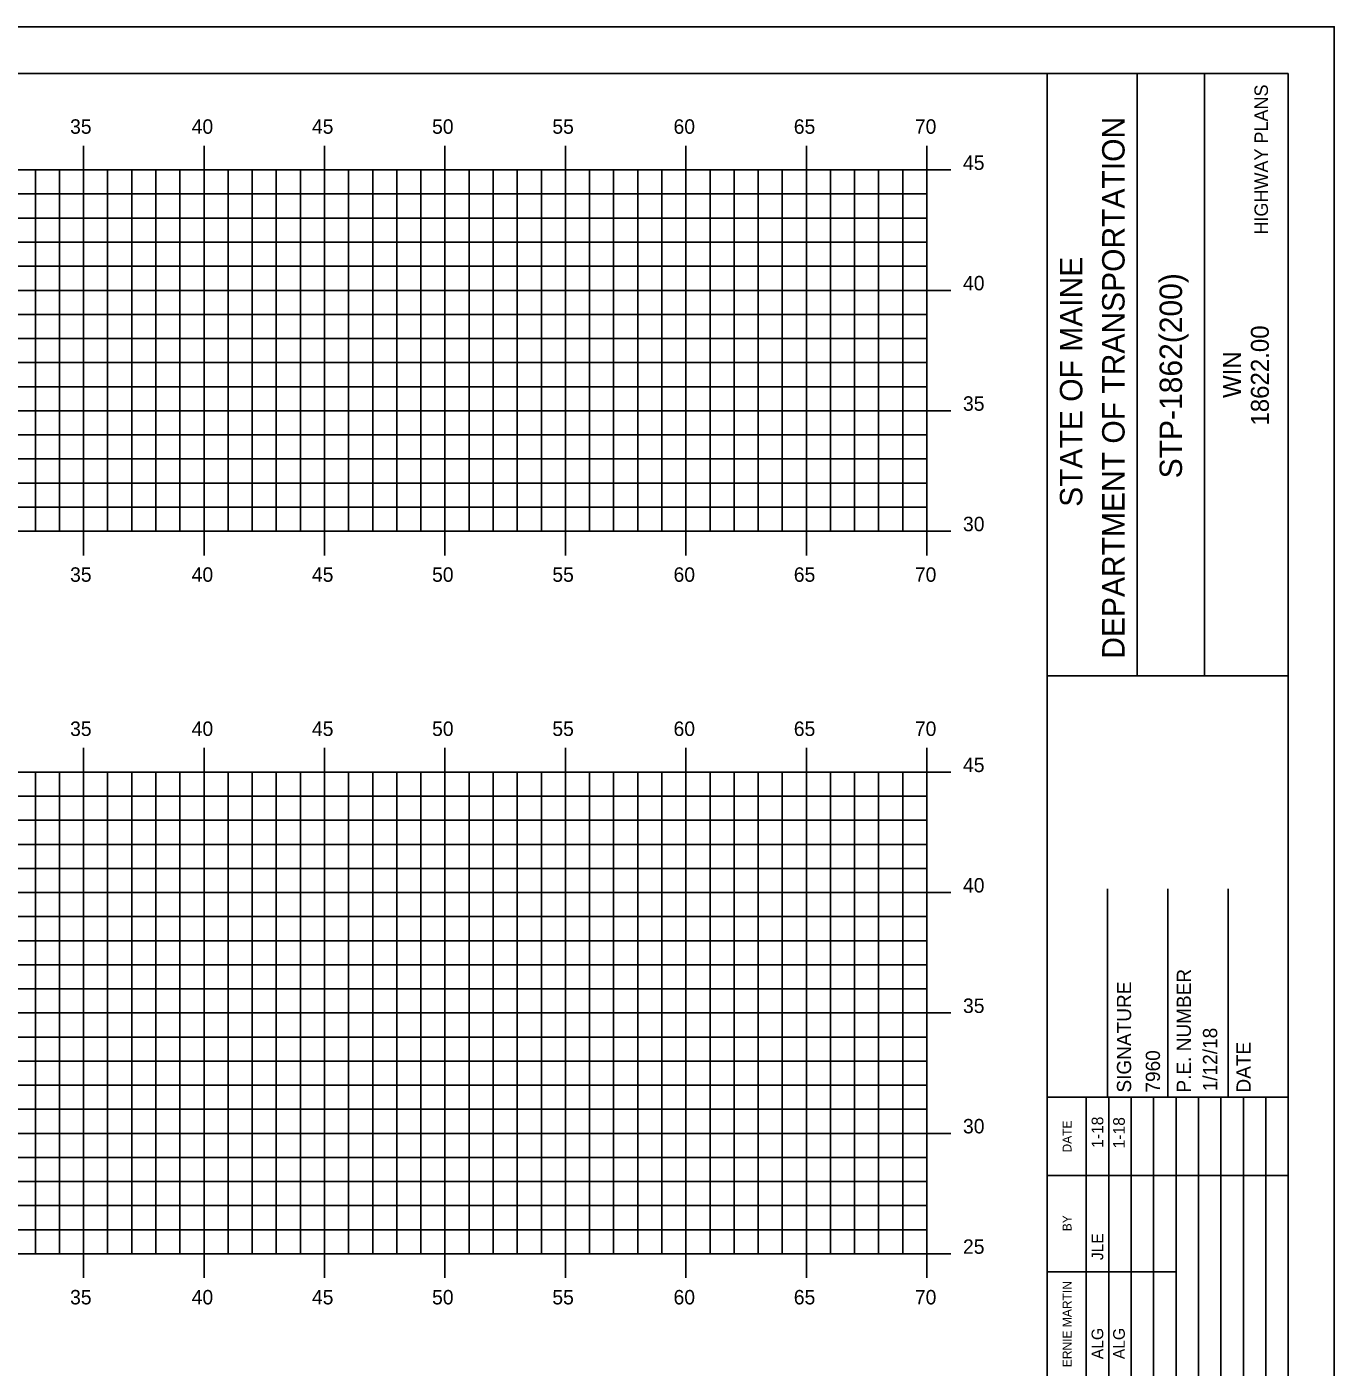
# Model space of a CAD drawing. Extents: x 1026799 to 1026969, y 394697 to 394807.
# Drawn here: x 1026915 to 1026969.3, y 394750.9 to 394806.5 of the extents above; entities that cross this region are included whole.
import ezdxf

# ---------------------------------------------------------------- set-up
doc = ezdxf.new("R2010")
doc.units = 0
for name, color, linetype in [('BORDER', 7, 'Continuous'), ('H_V ANNOTATION', 7, 'Continuous'), ('HIGHWAY_TITLE', 7, 'Continuous'), ('MAJOR', 7, 'Continuous'), ('MINOR', 7, 'Continuous'), ('PLOT BOUNDARY', 7, 'Continuous')]:
    doc.layers.add(name, color=color, linetype=linetype)

msp = doc.modelspace()

# ---------------------------------------------------------------- linework, layer by layer
at = {"layer": 'BORDER'}
for p, q in [((1026967.348, 394804.607), (1026807.348, 394804.607)), ((1026957.348, 394699.607), (1026957.348, 394804.61)), ((1026961.076, 394779.604), (1026961.076, 394804.604)), ((1026963.871, 394779.604), (1026963.871, 394804.604)), ((1026967.348, 394699.607), (1026967.348, 394804.607)), ((1026957.349, 394779.601), (1026967.348, 394779.601)), ((1026959.848, 394762.11), (1026959.848, 394770.757)), ((1026962.348, 394762.11), (1026962.348, 394770.757)), ((1026964.848, 394762.11), (1026964.848, 394770.757)), ((1026957.348, 394762.11), (1026967.348, 394762.11))]:
    msp.add_line(p, q, dxfattribs=at)
for points in [[(1026958.963, 394758.86), (1026958.963, 394762.11)], [(1026959.895, 394744.613), (1026959.895, 394762.11)], [(1026960.827, 394762.11), (1026960.827, 394744.613)], [(1026961.759, 394744.613), (1026961.759, 394762.11)], [(1026962.69, 394744.613), (1026962.69, 394762.11)], [(1026963.622, 394744.613), (1026963.622, 394762.11)], [(1026964.554, 394744.613), (1026964.554, 394762.11)], [(1026965.485, 394744.613), (1026965.485, 394762.11)], [(1026966.417, 394744.613), (1026966.417, 394762.11)], [(1026958.964, 394744.613), (1026958.964, 394761.404)], [(1026957.348, 394758.86), (1026967.348, 394758.86)], [(1026957.348, 394754.86), (1026958.964, 394754.86)], [(1026958.963, 394754.86), (1026962.689, 394754.86)]]:
    msp.add_lwpolyline(points, dxfattribs=at)
at = {"layer": 'MAJOR'}
for p, q in [((1026917.348, 394801.609), (1026917.348, 394800.607)), ((1026922.348, 394801.609), (1026922.348, 394800.607)), ((1026927.348, 394801.609), (1026927.348, 394800.607)), ((1026932.348, 394801.609), (1026932.348, 394800.607)), ((1026937.348, 394801.609), (1026937.348, 394800.607)), ((1026942.348, 394801.609), (1026942.348, 394800.607)), ((1026947.348, 394801.609), (1026947.348, 394800.607)), ((1026952.348, 394801.609), (1026952.348, 394800.607)), ((1026812.348, 394800.607), (1026952.348, 394800.607)), ((1026917.348, 394785.607), (1026917.348, 394800.607)), ((1026922.348, 394785.607), (1026922.348, 394800.607)), ((1026927.348, 394785.607), (1026927.348, 394800.607)), ((1026932.348, 394785.607), (1026932.348, 394800.607)), ((1026937.348, 394785.607), (1026937.348, 394800.607)), ((1026942.348, 394785.607), (1026942.348, 394800.607)), ((1026947.348, 394785.607), (1026947.348, 394800.607)), ((1026953.35, 394800.607), (1026951.346, 394800.607)), ((1026952.348, 394785.607), (1026952.348, 394800.607)), ((1026812.348, 394795.607), (1026952.348, 394795.607)), ((1026953.35, 394795.607), (1026951.346, 394795.607)), ((1026812.348, 394790.607), (1026952.348, 394790.607)), ((1026953.35, 394790.607), (1026951.346, 394790.607)), ((1026812.348, 394785.607), (1026952.348, 394785.607)), ((1026917.348, 394784.605), (1026917.348, 394785.607)), ((1026922.348, 394784.605), (1026922.348, 394785.607)), ((1026927.348, 394784.605), (1026927.348, 394785.607)), ((1026932.348, 394784.605), (1026932.348, 394785.607)), ((1026937.348, 394784.605), (1026937.348, 394785.607)), ((1026942.348, 394784.605), (1026942.348, 394785.607)), ((1026947.348, 394784.605), (1026947.348, 394785.607)), ((1026953.35, 394785.607), (1026951.346, 394785.607)), ((1026952.348, 394784.605), (1026952.348, 394785.607)), ((1026917.348, 394776.609), (1026917.348, 394775.607)), ((1026922.348, 394776.609), (1026922.348, 394775.607)), ((1026927.348, 394776.609), (1026927.348, 394775.607)), ((1026932.348, 394776.609), (1026932.348, 394775.607)), ((1026937.348, 394776.609), (1026937.348, 394775.607)), ((1026942.348, 394776.609), (1026942.348, 394775.607)), ((1026947.348, 394776.609), (1026947.348, 394775.607)), ((1026952.348, 394776.609), (1026952.348, 394775.607)), ((1026812.348, 394775.607), (1026952.348, 394775.607)), ((1026917.348, 394755.607), (1026917.348, 394775.607)), ((1026922.348, 394755.607), (1026922.348, 394775.607)), ((1026927.348, 394755.607), (1026927.348, 394775.607)), ((1026932.348, 394755.607), (1026932.348, 394775.607)), ((1026937.348, 394755.607), (1026937.348, 394775.607)), ((1026942.348, 394755.607), (1026942.348, 394775.607)), ((1026947.348, 394755.607), (1026947.348, 394775.607)), ((1026953.35, 394775.607), (1026951.346, 394775.607)), ((1026952.348, 394755.607), (1026952.348, 394775.607)), ((1026812.348, 394770.607), (1026952.348, 394770.607)), ((1026953.35, 394770.607), (1026951.346, 394770.607)), ((1026812.348, 394765.607), (1026952.348, 394765.607)), ((1026953.35, 394765.607), (1026951.346, 394765.607)), ((1026812.348, 394760.607), (1026952.348, 394760.607)), ((1026953.35, 394760.607), (1026951.346, 394760.607)), ((1026812.348, 394755.607), (1026952.348, 394755.607)), ((1026917.348, 394754.605), (1026917.348, 394755.607)), ((1026922.348, 394754.605), (1026922.348, 394755.607)), ((1026927.348, 394754.605), (1026927.348, 394755.607)), ((1026932.348, 394754.605), (1026932.348, 394755.607)), ((1026937.348, 394754.605), (1026937.348, 394755.607)), ((1026942.348, 394754.605), (1026942.348, 394755.607)), ((1026947.348, 394754.605), (1026947.348, 394755.607)), ((1026953.35, 394755.607), (1026951.346, 394755.607)), ((1026952.348, 394754.605), (1026952.348, 394755.607))]:
    msp.add_line(p, q, dxfattribs=at)
at = {"layer": 'MINOR'}
for p, q in [((1026915.348, 394785.607), (1026915.348, 394800.607)), ((1026916.348, 394785.607), (1026916.348, 394800.607)), ((1026918.348, 394785.607), (1026918.348, 394800.607)), ((1026919.348, 394785.607), (1026919.348, 394800.607)), ((1026920.348, 394785.607), (1026920.348, 394800.607)), ((1026921.348, 394785.607), (1026921.348, 394800.607)), ((1026923.348, 394785.607), (1026923.348, 394800.607)), ((1026924.348, 394785.607), (1026924.348, 394800.607)), ((1026925.348, 394785.607), (1026925.348, 394800.607)), ((1026926.348, 394785.607), (1026926.348, 394800.607)), ((1026928.348, 394785.607), (1026928.348, 394800.607)), ((1026929.348, 394785.607), (1026929.348, 394800.607)), ((1026930.348, 394785.607), (1026930.348, 394800.607)), ((1026931.348, 394785.607), (1026931.348, 394800.607)), ((1026933.348, 394785.607), (1026933.348, 394800.607)), ((1026934.348, 394785.607), (1026934.348, 394800.607)), ((1026935.348, 394785.607), (1026935.348, 394800.607)), ((1026936.348, 394785.607), (1026936.348, 394800.607)), ((1026938.348, 394785.607), (1026938.348, 394800.607)), ((1026939.348, 394785.607), (1026939.348, 394800.607)), ((1026940.348, 394785.607), (1026940.348, 394800.607)), ((1026941.348, 394785.607), (1026941.348, 394800.607)), ((1026943.348, 394785.607), (1026943.348, 394800.607)), ((1026944.348, 394785.607), (1026944.348, 394800.607)), ((1026945.348, 394785.607), (1026945.348, 394800.607)), ((1026946.348, 394785.607), (1026946.348, 394800.607)), ((1026948.348, 394785.607), (1026948.348, 394800.607)), ((1026949.348, 394785.607), (1026949.348, 394800.607)), ((1026950.348, 394785.607), (1026950.348, 394800.607)), ((1026951.348, 394785.607), (1026951.348, 394800.607)), ((1026812.348, 394799.607), (1026952.348, 394799.607)), ((1026952.348, 394799.607), (1026951.346, 394799.607)), ((1026812.348, 394798.607), (1026952.348, 394798.607)), ((1026952.348, 394798.607), (1026951.346, 394798.607)), ((1026812.348, 394797.607), (1026952.348, 394797.607)), ((1026952.348, 394797.607), (1026951.346, 394797.607)), ((1026812.348, 394796.607), (1026952.348, 394796.607)), ((1026952.348, 394796.607), (1026951.346, 394796.607)), ((1026812.348, 394794.607), (1026952.348, 394794.607)), ((1026952.348, 394794.607), (1026951.346, 394794.607)), ((1026812.348, 394793.607), (1026952.348, 394793.607)), ((1026952.348, 394793.607), (1026951.346, 394793.607)), ((1026812.348, 394792.607), (1026952.348, 394792.607)), ((1026952.348, 394792.607), (1026951.346, 394792.607)), ((1026812.348, 394791.607), (1026952.348, 394791.607)), ((1026952.348, 394791.607), (1026951.346, 394791.607)), ((1026812.348, 394789.607), (1026952.348, 394789.607)), ((1026952.348, 394789.607), (1026951.346, 394789.607)), ((1026812.348, 394788.607), (1026952.348, 394788.607)), ((1026952.348, 394788.607), (1026951.346, 394788.607)), ((1026812.348, 394787.607), (1026952.348, 394787.607)), ((1026952.348, 394787.607), (1026951.346, 394787.607)), ((1026812.348, 394786.607), (1026952.348, 394786.607)), ((1026952.348, 394786.607), (1026951.346, 394786.607)), ((1026915.348, 394755.607), (1026915.348, 394775.607)), ((1026916.348, 394755.607), (1026916.348, 394775.607)), ((1026918.348, 394755.607), (1026918.348, 394775.607)), ((1026919.348, 394755.607), (1026919.348, 394775.607)), ((1026920.348, 394755.607), (1026920.348, 394775.607)), ((1026921.348, 394755.607), (1026921.348, 394775.607)), ((1026923.348, 394755.607), (1026923.348, 394775.607)), ((1026924.348, 394755.607), (1026924.348, 394775.607)), ((1026925.348, 394755.607), (1026925.348, 394775.607)), ((1026926.348, 394755.607), (1026926.348, 394775.607)), ((1026928.348, 394755.607), (1026928.348, 394775.607)), ((1026929.348, 394755.607), (1026929.348, 394775.607)), ((1026930.348, 394755.607), (1026930.348, 394775.607)), ((1026931.348, 394755.607), (1026931.348, 394775.607)), ((1026933.348, 394755.607), (1026933.348, 394775.607)), ((1026934.348, 394755.607), (1026934.348, 394775.607)), ((1026935.348, 394755.607), (1026935.348, 394775.607)), ((1026936.348, 394755.607), (1026936.348, 394775.607)), ((1026938.348, 394755.607), (1026938.348, 394775.607)), ((1026939.348, 394755.607), (1026939.348, 394775.607)), ((1026940.348, 394755.607), (1026940.348, 394775.607)), ((1026941.348, 394755.607), (1026941.348, 394775.607)), ((1026943.348, 394755.607), (1026943.348, 394775.607)), ((1026944.348, 394755.607), (1026944.348, 394775.607)), ((1026945.348, 394755.607), (1026945.348, 394775.607)), ((1026946.348, 394755.607), (1026946.348, 394775.607)), ((1026948.348, 394755.607), (1026948.348, 394775.607)), ((1026949.348, 394755.607), (1026949.348, 394775.607)), ((1026950.348, 394755.607), (1026950.348, 394775.607)), ((1026951.348, 394755.607), (1026951.348, 394775.607)), ((1026812.348, 394774.607), (1026952.348, 394774.607)), ((1026952.348, 394774.607), (1026951.346, 394774.607)), ((1026812.348, 394773.607), (1026952.348, 394773.607)), ((1026952.348, 394773.607), (1026951.346, 394773.607)), ((1026812.348, 394772.607), (1026952.348, 394772.607)), ((1026952.348, 394772.607), (1026951.346, 394772.607)), ((1026812.348, 394771.607), (1026952.348, 394771.607)), ((1026952.348, 394771.607), (1026951.346, 394771.607)), ((1026812.348, 394769.607), (1026952.348, 394769.607)), ((1026952.348, 394769.607), (1026951.346, 394769.607)), ((1026812.348, 394768.607), (1026952.348, 394768.607)), ((1026952.348, 394768.607), (1026951.346, 394768.607)), ((1026812.348, 394767.607), (1026952.348, 394767.607)), ((1026952.348, 394767.607), (1026951.346, 394767.607)), ((1026812.348, 394766.607), (1026952.348, 394766.607)), ((1026952.348, 394766.607), (1026951.346, 394766.607)), ((1026812.348, 394764.607), (1026952.348, 394764.607)), ((1026952.348, 394764.607), (1026951.346, 394764.607)), ((1026812.348, 394763.607), (1026952.348, 394763.607)), ((1026952.348, 394763.607), (1026951.346, 394763.607)), ((1026812.348, 394762.607), (1026952.348, 394762.607)), ((1026952.348, 394762.607), (1026951.346, 394762.607)), ((1026812.348, 394761.607), (1026952.348, 394761.607)), ((1026952.348, 394761.607), (1026951.346, 394761.607)), ((1026812.348, 394759.607), (1026952.348, 394759.607)), ((1026952.348, 394759.607), (1026951.346, 394759.607)), ((1026812.348, 394758.607), (1026952.348, 394758.607)), ((1026952.348, 394758.607), (1026951.346, 394758.607)), ((1026812.348, 394757.607), (1026952.348, 394757.607)), ((1026952.348, 394757.607), (1026951.346, 394757.607)), ((1026812.348, 394756.607), (1026952.348, 394756.607)), ((1026952.348, 394756.607), (1026951.346, 394756.607))]:
    msp.add_line(p, q, dxfattribs=at)
at = {"layer": 'PLOT BOUNDARY'}
msp.add_lwpolyline([(1026799.254, 394696.548), (1026969.254, 394696.548), (1026969.254, 394806.548), (1026799.254, 394806.548)], close=True, dxfattribs=at)

# ---------------------------------------------------------------- texts
at = {"layer": 'BORDER'}
for s, height, p in [('DEPARTMENT OF TRANSPORTATION', 0.93176, (1026960.555, 394780.313)), ('STATE OF MAINE', 0.93176, (1026958.803, 394786.619)), ('STP-1862(200)', 0.93176, (1026962.94, 394787.801)), ('18622.00', 0.7453, (1026966.543, 394789.993)), ('WIN', 0.7453, (1026965.385, 394791.137)), ('P.E. NUMBER', 0.59055, (1026963.309, 394762.302)), ('SIGNATURE', 0.5906, (1026960.828, 394762.302)), ('1/12/18', 0.5906, (1026964.398, 394762.357)), ('7960', 0.5906, (1026962.025, 394762.302)), ('DATE', 0.5906, (1026965.789, 394762.302)), ('1-18', 0.4845, (1026959.671, 394760.007)), ('1-18', 0.4845, (1026960.565, 394759.985)), ('DATE', 0.3714, (1026958.352, 394759.815)), ('BY', 0.3714, (1026958.352, 394756.545)), ('JLE', 0.4845, (1026959.671, 394755.345)), ('ERNIE MARTIN', 0.37275, (1026958.352, 394750.901)), ('ALG', 0.4845, (1026959.671, 394751.233)), ('ALG', 0.4845, (1026960.565, 394751.233))]:
    msp.add_text(s, height=height, rotation=90, dxfattribs=at).set_placement(p)
at = {"layer": 'H_V ANNOTATION'}
for s, p in [('35', (1026916.788, 394802.107)), ('40', (1026921.834, 394802.107)), ('45', (1026926.826, 394802.107)), ('50', (1026931.812, 394802.107)), ('55', (1026936.804, 394802.107)), ('60', (1026941.834, 394802.107)), ('65', (1026946.826, 394802.107)), ('70', (1026951.85, 394802.107)), ('45', (1026953.848, 394800.607)), ('40', (1026953.848, 394795.607)), ('35', (1026953.848, 394790.607)), ('30', (1026953.848, 394785.607)), ('35', (1026916.788, 394783.507)), ('40', (1026921.834, 394783.507)), ('45', (1026926.826, 394783.507)), ('50', (1026931.812, 394783.507)), ('55', (1026936.804, 394783.507)), ('60', (1026941.834, 394783.507)), ('65', (1026946.826, 394783.507)), ('70', (1026951.85, 394783.507)), ('35', (1026916.788, 394777.107)), ('40', (1026921.834, 394777.107)), ('45', (1026926.826, 394777.107)), ('50', (1026931.812, 394777.107)), ('55', (1026936.804, 394777.107)), ('60', (1026941.834, 394777.107)), ('65', (1026946.826, 394777.107)), ('70', (1026951.85, 394777.107)), ('45', (1026953.848, 394775.607)), ('40', (1026953.848, 394770.607)), ('35', (1026953.848, 394765.607)), ('30', (1026953.848, 394760.607)), ('25', (1026953.848, 394755.607)), ('35', (1026916.788, 394753.507)), ('40', (1026921.834, 394753.507)), ('45', (1026926.826, 394753.507)), ('50', (1026931.812, 394753.507)), ('55', (1026936.804, 394753.507)), ('60', (1026941.834, 394753.507)), ('65', (1026946.826, 394753.507)), ('70', (1026951.85, 394753.507))]:
    msp.add_text(s, height=0.6, dxfattribs=at).set_placement(p)
at = {"layer": 'HIGHWAY_TITLE'}
msp.add_text('HIGHWAY PLANS', height=0.55901, rotation=90, dxfattribs=at).set_placement((1026966.506, 394797.922))

doc.saveas('drawing.dxf')
